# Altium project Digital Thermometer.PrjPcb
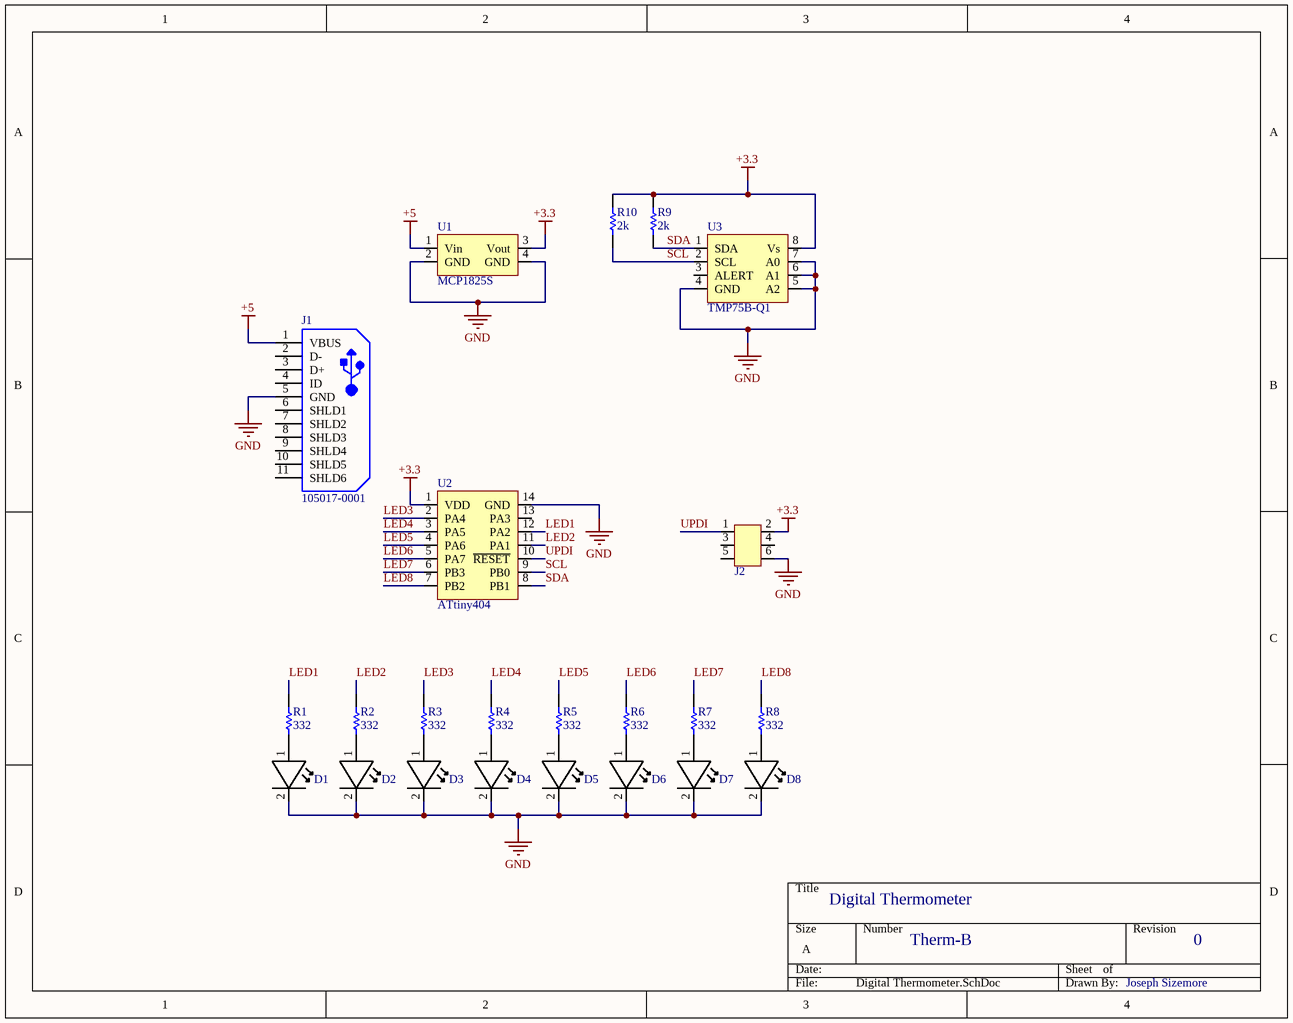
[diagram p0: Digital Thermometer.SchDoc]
1 sheet, 23 parts. Net scope: global (net labels, ports and power ports of the same name join across sheets).
Board file: Therm-B0.PcbDoc

## Sheet Digital Thermometer.SchDoc
size A

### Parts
D1  LED  [LED]  (value not drawn)
D2  LED  [LED]  (value not drawn)
D3  LED  [LED]  (value not drawn)
D4  LED  [LED]  (value not drawn)
D5  LED  [LED]  (value not drawn)
D6  LED  [LED]  (value not drawn)
D7  LED  [LED]  (value not drawn)
D8  LED  [LED]  (value not drawn)
J1  105017-0001  [USB-MICRO-B_V]
J2  Header  [2x3 Header Straight Pin ZigZag]  (value not drawn)
R1  332  [RESC1608X55X25NL10T15]
R2  332  [RESC1608X55X25NL10T15]
R3  332  [RESC1608X55X25NL10T15]
R4  332  [RESC1608X55X25NL10T15]
R5  332  [RESC1608X55X25NL10T15]
R6  332  [RESC1608X55X25NL10T15]
R7  332  [RESC1608X55X25NL10T15]
R8  332  [RESC1608X55X25NL10T15]
R9  2k  [RESC1608X55X25NL10T15]
R10  2k  [RESC1608X55X25NL10T15]
U1  MCP1825S  [SOT-223-3]
U2  ATtiny404  [14-PIN SOIC 150]
U3  TMP75B-Q1  [8-Pin SOIC 150]

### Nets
+3.3: J2.2 R9.2 R10.2 U1.3(Vout) U2.1(VDD) U3.8(Vs)
+5: J1.1(VBUS) U1.1(Vin)
GND: D1.2(Cathode) D2.2(Cathode) D3.2(Cathode) D4.2(Cathode) D5.2(Cathode) D6.2(Cathode) D7.2(Cathode) D8.2(Cathode) J1.5(GND) J2.6 U1.2(GND) U1.4(GND) U2.14(GND) U3.4(GND) U3.5(A2) U3.6(A1) U3.7(A0)
LED1: R1.2 U2.12(PA2)
LED2: R2.2 U2.11(PA1)
LED3: R3.2 U2.2(PA4)
LED4: R4.2 U2.3(PA5)
LED5: R5.2 U2.4(PA6)
LED6: R6.2 U2.5(PA7)
LED7: R7.2 U2.6(PB3)
LED8: R8.2 U2.7(PB2)
SCL: R10.1 U2.9(PB0) U3.2(SCL)
SDA: R9.1 U2.8(PB1) U3.1(SDA)
UPDI: J2.1 U2.10(~{RESET})
NetD1_1: D1.1(Anode) R1.1
NetD2_1: D2.1(Anode) R2.1
NetD3_1: D3.1(Anode) R3.1
NetD4_1: D4.1(Anode) R4.1
NetD5_1: D5.1(Anode) R5.1
NetD6_1: D6.1(Anode) R6.1
NetD7_1: D7.1(Anode) R7.1
NetD8_1: D8.1(Anode) R8.1

Not connected (* = marked no-connect by the designer): J1 2(D-) 3(D+) 4(ID) 6(SHLD1) 7(SHLD2) 8(SHLD3) 9(SHLD4) 10(SHLD5) 11(SHLD6); J2 3 4 5; U2 13(PA3); U3 3(ALERT)

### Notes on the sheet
- Digital Thermometer
- Therm-B
- 0
- Joseph Sizemore

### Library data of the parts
J1 = CMP-2000-05827-1: Micro-USB B Receptacle, Right Angle, Bottom Mount, Surface Mount, with Solder Tabs, -30 to 85 degC, 5-Pin USB, RoHS, Tape and Reel; Manufacturer: Molex; Featured Product: Micro-USBConnectorsUSBConnectors; Other Names: WM1399DKR; Package Version: Rev. F, 12/2012; Number of Contacts: 5; Connector Type: USB-microB; Catalog Drawings: 1050170001; 3D Model: 105017-0001.stp; Mating Products: WM17145-ND-CABLEMICROUSBBTOSTDA1.0MWM17147-ND-CABLEMICROUSBBTOSTDA2.0MWM17146-ND-CABLEMICROUSBBTOSTDA1.5M; PCN Assembly/Origin: ResinSupplier21/Oct/2015; Voltage - Max: 30V; Online Catalog: Molex-MicroUSB
J2 = 2x3 Header Straight Pin ZigZag
R1-R8 = CMP-2000-04013-1: Part Number: RC0603FR-07332RL; Manufacturer: Yageo
R9 R10 = CMP-2000-04259-1: Part Number: RC0603JR-072KL; Manufacturer: Yageo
